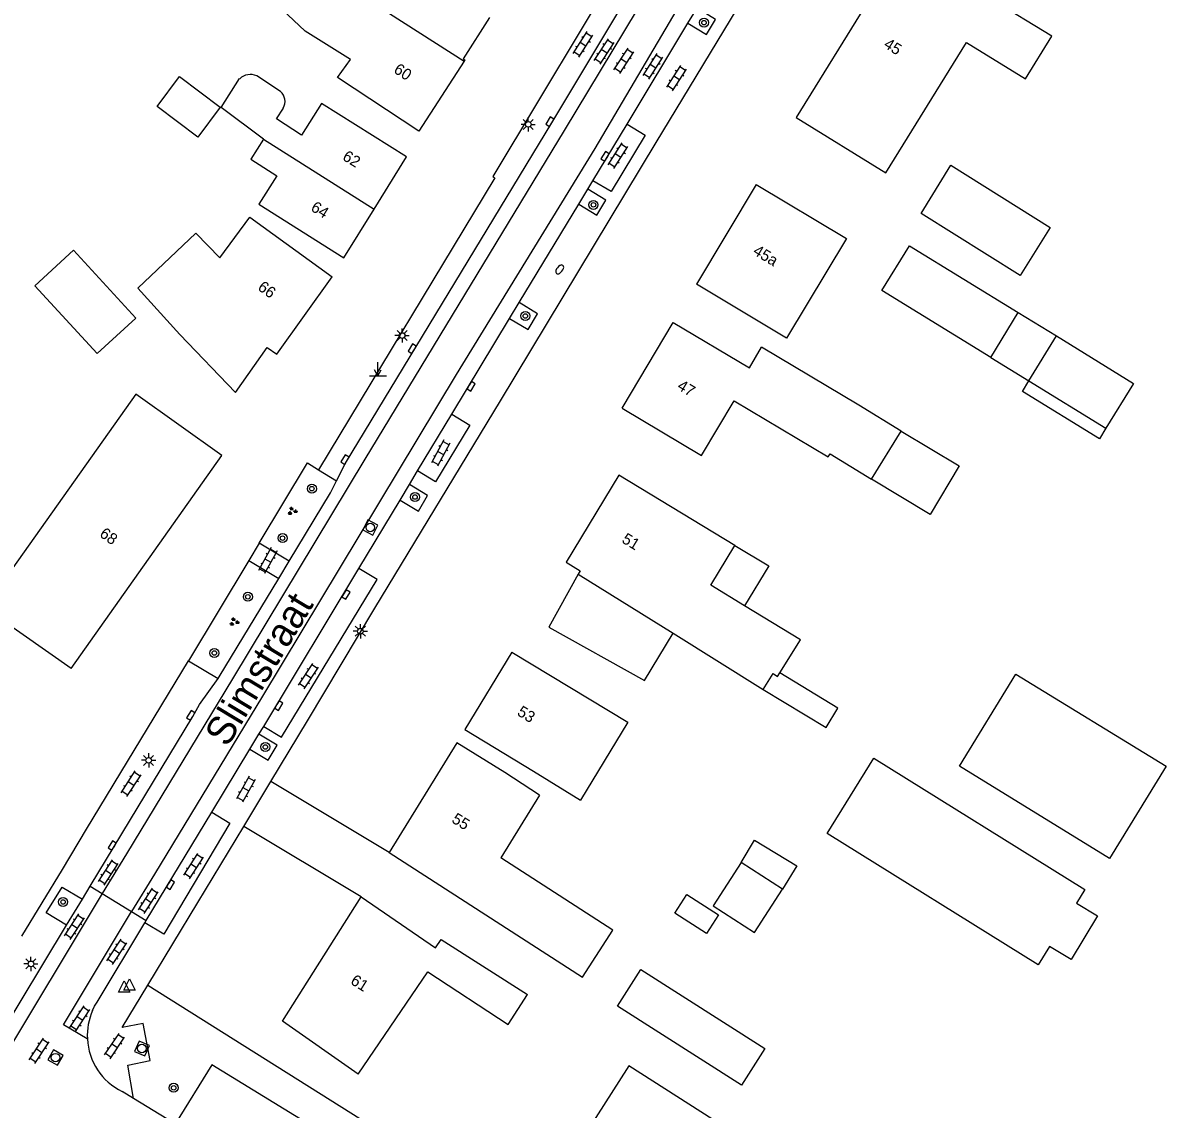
# Model space of a CAD drawing. Extents: x 136000 to 141014, y 402000 to 403500.
# Drawn here: x 137697.7 to 137798.8, y 402166.6 to 402262.7 of the extents above; entities that cross this region are included whole.
import ezdxf

# ---------------------------------------------------------------- set-up
doc = ezdxf.new("R2010")
doc.units = 0
for name, color, linetype in [('gg-afsc-erfafscheiding', 7, 'Continuous'), ('gg-anno-huisnummerreeks BGT', 7, 'Continuous'), ('gg-anno-openbare ruimte label', 7, 'Continuous'), ('gg-bbg-bijgebouw', 7, 'Continuous'), ('gg-bbg-gedigitaliseerde bebouwing', 7, 'Continuous'), ('gg-bbg-gedigitaliseerde bijgebouw', 7, 'Continuous'), ('gg-bbg-hoofdgebouw', 7, 'Continuous'), ('gg-bbg-luifel en loopbrug', 7, 'Continuous'), ('gg-bbg-tussenscheiding', 7, 'Continuous'), ('gg-knt-onverhard', 7, 'Continuous'), ('gg-knt-verharding', 7, 'Continuous'), ('gg-knt-verharding nz', 7, 'Continuous'), ('gt-symb-boom', 7, 'Continuous'), ('gt-symb-brandkraan', 7, 'Continuous'), ('gt-symb-groenvak', 7, 'Continuous'), ('gt-symb-klinker verharding', 7, 'Continuous'), ('gt-symb-kolk', 7, 'Continuous'), ('gt-symb-lichtmast', 7, 'Continuous'), ('gt-symb-markant object', 7, 'Continuous'), ('gt-symb-rioolschacht', 7, 'Continuous'), ('gt-symb-waterafsluiter', 7, 'Continuous')]:
    doc.layers.add(name, color=color, linetype=linetype)

# ---------------------------------------------------------------- blocks, each defined once
blk = doc.blocks.new('gt0-BOOM')
at = {"layer": 'gt-symb-boom'}
for radius in [0.4, 0.2]:
    blk.add_circle((0, 0), radius, dxfattribs=at)
blk = doc.blocks.new('gt0-BR')
at = {"layer": 'gt-symb-brandkraan'}
for centre, radius, start, end in [((-0.24, 0), 0.206, 107.5669, 252.4331), ((0.6, -2.66), 3, 106.892, 107.5669), ((0, -0.69), 0.938, 73.108, 106.892), ((-0.6, -2.66), 3, 72.4331, 73.108), ((0.24, 0), 0.206, 287.567, 72.4331), ((0.6, 2.66), 3, 252.4331, 253.108), ((0, 0.69), 0.938, 253.108, 286.8921), ((-0.6, 2.66), 3, 286.8921, 287.567)]:
    blk.add_arc(centre, radius, start, end, dxfattribs=at)
blk = doc.blocks.new('gt0-LMAST')
at = {"layer": 'gt-symb-lichtmast'}
for p, q in [((-0.18, 0.17), (-0.45, 0.44)), ((0, 0.25), (0, 0.62)), ((0.17, 0.17), (0.44, 0.44)), ((-0.25, 0), (-0.63, 0)), ((-0.18, -0.18), (-0.45, -0.45)), ((0, -0.25), (0, -0.63)), ((0.44, -0.45), (0.17, -0.18)), ((0.25, 0), (0.62, 0))]:
    blk.add_line(p, q, dxfattribs=at)
blk.add_circle((0, 0), 0.25, dxfattribs=at)
blk = doc.blocks.new('gt0-KOLK')
at = {"layer": 'gt-symb-kolk'}
blk.add_lwpolyline([(0, 0), (0.38, 0), (0.38, 0.4), (-0.37, 0.4), (-0.37, 0), (0, 0)], dxfattribs=at)
blk = doc.blocks.new('gt0-KL1')
at = {"layer": 'gt-symb-klinker verharding'}
for p, q in [((-1.15, 0.3), (1.15, 0.3)), ((-1, -0.3), (-1, 0.3)), ((-0.5, 0.3), (-0.5, 0.45)), ((0, -0.3), (0, 0.3)), ((0.5, 0.3), (0.5, 0.45)), ((1, -0.3), (1, 0.3)), ((-1.15, -0.3), (1.15, -0.3)), ((-0.5, -0.45), (-0.5, -0.3)), ((0.5, -0.45), (0.5, -0.3))]:
    blk.add_line(p, q, dxfattribs=at)
blk = doc.blocks.new('gt0-GRVAK')
at = {"layer": 'gt-symb-groenvak'}
for p, q in [((-0.11, 0.19), (-0.23, 0.24)), ((-0.18, 0.15), (0.09, 0.15)), ((-0.09, 0.21), (-0.16, 0.32)), ((-0.05, 0.21), (-0.05, 0.39)), ((0, 0.21), (0.06, 0.32)), ((0.02, 0.19), (0.13, 0.24)), ((0.26, -0.05), (0.2, 0.06)), ((0.31, -0.05), (0.31, 0.13)), ((0.35, -0.05), (0.41, 0.06)), ((-0.24, -0.23), (-0.36, -0.18)), ((-0.32, -0.26), (-0.05, -0.26)), ((-0.23, -0.21), (-0.29, -0.1)), ((-0.18, -0.2), (-0.18, -0.02)), ((-0.14, -0.21), (-0.07, -0.1)), ((-0.12, -0.23), (0, -0.18)), ((0.24, -0.07), (0.12, -0.02)), ((0.17, -0.11), (0.44, -0.11)), ((0.37, -0.07), (0.49, -0.02))]:
    blk.add_line(p, q, dxfattribs=at)
blk = doc.blocks.new('gt0-RS')
at = {"layer": 'gt-symb-rioolschacht'}
blk.add_lwpolyline([(-0.5, -0.5), (0.5, -0.5), (0.5, 0.5), (-0.5, 0.5)], close=True, dxfattribs=at)
blk.add_circle((0, 0), 0.375, dxfattribs=at)
blk = doc.blocks.new('gt0-WAFSL')
at = {"layer": 'gt-symb-waterafsluiter'}
for p, q in [((-0.5, -0.33), (0, 0.67)), ((0, 0.67), (0.5, -0.33)), ((0.5, -0.33), (-0.5, -0.33))]:
    blk.add_line(p, q, dxfattribs=at)
blk = doc.blocks.new('gt0-MARKOB')
at = {"layer": 'gt-symb-markant object'}
for p, q in [((0, 0), (0, 1.2)), ((-0.75, 0), (0.75, 0)), ((0, 0), (-0.3, 0.52)), ((0, 0), (0.3, 0.52))]:
    blk.add_line(p, q, dxfattribs=at)

msp = doc.modelspace()

# ---------------------------------------------------------------- linework, layer by layer
at = {"layer": 'gg-afsc-erfafscheiding'}
msp.add_lwpolyline([(137708.78, 402177.58), (137742.87, 402156.14), (137738.17, 402148.85)], dxfattribs=at)
at = {"layer": 'gg-bbg-bijgebouw'}
for p, q in [((137783.33, 402233.13), (137785.77, 402237.09)), ((137786.71, 402231.06), (137789.14, 402235.02)), ((137786.71, 402231.06), (137793.52, 402226.87))]:
    msp.add_line(p, q, dxfattribs=at)
for points in [[(137783.33, 402233.13), (137773.71, 402239.05), (137776.15, 402243.01), (137785.77, 402237.09)], [(137789.14, 402235.02), (137795.96, 402230.83), (137793.52, 402226.87)]]:
    msp.add_lwpolyline(points, dxfattribs=at)
at = {"layer": 'gg-bbg-gedigitaliseerde bebouwing'}
for p, q in [((137720.52, 402256.64), (137718.43, 402258.05)), ((137720.16, 402254.22), (137720.78, 402255.18)), ((137771.67, 402228.9), (137763.07, 402234.02)), ((137775.4, 402226.61), (137771.67, 402228.9)), ((137772.78, 402222.35), (137775.4, 402226.61)), ((137769.12, 402224.6), (137772.78, 402222.35)), ((137760.71, 402216.5), (137750.45, 402222.72)), ((137758.58, 402212.99), (137760.71, 402216.5)), ((137761.57, 402211.16), (137758.58, 402212.99)), ((137755.24, 402208.72), (137763.22, 402203.75)), ((137736.82, 402200.2), (137742.91, 402196.52)), ((137742.91, 402196.52), (137747.07, 402193.96)), ((137743.42, 402194.41), (137740.01, 402188.85))]:
    msp.add_line(p, q, dxfattribs=at)
for points in [[(137732.75, 402253.14), (137725.58, 402257.9), (137726.72, 402259.49), (137722.72, 402262), (137715.62, 402268.68), (137716.12, 402269.16), (137711.53, 402274.03)], [(137766.14, 402254.34), (137774.07, 402249.44), (137781.2, 402260.99), (137786.42, 402257.77), (137788.74, 402261.54), (137783.41, 402264.83), (137784.31, 402266.3), (137776.5, 402271.13)], [(137719.01, 402252.42), (137715.27, 402255.22), (137716.91, 402257.79)], [(137731.68, 402250.87), (137724.16, 402255.6), (137722.37, 402252.8), (137720.16, 402254.22)], [(137719.01, 402252.42), (137717.89, 402250.67), (137720.21, 402249.19), (137718.6, 402246.67), (137726.13, 402241.93)], [(137715.16, 402241.93), (137717.82, 402245.52), (137725.09, 402240.24)], [(137707.92, 402239.25), (137713.05, 402244.13), (137715.16, 402241.93)], [(137716.54, 402230.03), (137711.62, 402235.16), (137707.92, 402239.25)], [(137715.34, 402224.45), (137707.73, 402229.86), (137694.33, 402210.97)], [(137750.75, 402228.64), (137757.77, 402224.46), (137760.64, 402229.27), (137768.95, 402224.33), (137769.12, 402224.6)], [(137764.68, 402205.21), (137766.5, 402208.13), (137761.57, 402211.16)], [(137744.26, 402209.27), (137752.71, 402204.54), (137755.24, 402208.72)], [(137740.97, 402207.06), (137751.24, 402200.85), (137747.07, 402193.96)], [(137763.22, 402203.75), (137764.09, 402205.15), (137764.49, 402204.9), (137764.68, 402205.21)], [(137743.42, 402194.41), (137740.37, 402196.4), (137736.11, 402199.03)], [(137747.23, 402178.29), (137749.92, 402182.46), (137740.01, 402188.85)], [(137727.39, 402169.72), (137733.55, 402178.78), (137740.66, 402174.12), (137742.36, 402176.77)]]:
    msp.add_lwpolyline(points, dxfattribs=at)
for centre, radius, start, end in [((137717.89, 402256.68), 1.47, 68.4356, 131.4426), ((137719.78, 402255.76), 1.15, 329.9501, 50.1062)]:
    msp.add_arc(centre, radius, start, end, dxfattribs=at)
at = {"layer": 'gg-bbg-gedigitaliseerde bijgebouw'}
for p, q in [((137761.26, 402188.45), (137758.78, 402184.6)), ((137764.93, 402186.08), (137761.26, 402188.45))]:
    msp.add_line(p, q, dxfattribs=at)
for points in [[(137709.61, 402255.31), (137711.6, 402257.97), (137715.2, 402255.27), (137713.21, 402252.61), (137709.61, 402255.31)], [(137788.6, 402244.61), (137785.93, 402240.36), (137777.17, 402245.86), (137779.82, 402250.12), (137788.6, 402244.61)], [(137698.79, 402239.47), (137702.21, 402242.62), (137707.74, 402236.61), (137704.32, 402233.46), (137698.79, 402239.47)], [(137780.56, 402196.96), (137785.55, 402205.11), (137798.85, 402196.95), (137793.85, 402188.8), (137780.56, 402196.96)], [(137768.87, 402191.02), (137773.01, 402197.66), (137791.67, 402186.04), (137790.91, 402184.83)], [(137788.53, 402181.01), (137787.53, 402179.4), (137768.87, 402191.02)], [(137758.78, 402184.6), (137762.45, 402182.24), (137764.93, 402186.08)], [(137755.41, 402183.96), (137756.46, 402185.6), (137759.25, 402183.8), (137758.19, 402182.17), (137755.41, 402183.96)], [(137790.91, 402184.83), (137792.77, 402183.71), (137790.44, 402179.86), (137788.53, 402181.01)], [(137750.33, 402175.74), (137752.4, 402178.99), (137763.37, 402171.99), (137761.3, 402168.74), (137750.33, 402175.74)], [(137747.73, 402164.81), (137751.49, 402162.41), (137753.41, 402165.41), (137757.07, 402163.07), (137758.75, 402165.7), (137751.32, 402170.44), (137747.73, 402164.81)]]:
    msp.add_lwpolyline(points, dxfattribs=at)
at = {"layer": 'gg-bbg-hoofdgebouw'}
for p, q in [((137776.5, 402271.13), (137766.14, 402254.34)), ((137736.78, 402259.32), (137732.75, 402253.14)), ((137728.8, 402246.23), (137731.68, 402250.87)), ((137762.6, 402248.41), (137757.3, 402239.6)), ((137726.13, 402241.93), (137728.8, 402246.23)), ((137702, 402205.61), (137715.34, 402224.45)), ((137746.86, 402213.94), (137744.26, 402209.27)), ((137702, 402205.61), (137694.33, 402210.97)), ((137740.97, 402207.06), (137736.82, 402200.2)), ((137736.11, 402199.03), (137730.13, 402189.32)), ((137730.13, 402189.32), (137747.23, 402178.29))]:
    msp.add_line(p, q, dxfattribs=at)
for points in [[(137739.02, 402263.2), (137736.68, 402259.53), (137736.85, 402259.42), (137736.78, 402259.32)], [(137762.6, 402248.41), (137770.59, 402243.64), (137765.27, 402234.83), (137757.3, 402239.6)], [(137716.54, 402230.03), (137719.35, 402233.99), (137720.2, 402233.41), (137725.09, 402240.24)], [(137750.75, 402228.64), (137755.26, 402236.21), (137761.99, 402232.2), (137763.07, 402234.02)], [(137750.45, 402222.72), (137745.78, 402215.02), (137747.04, 402214.25), (137746.86, 402213.94)], [(137727.39, 402169.72), (137720.7, 402174.39), (137727.66, 402185.41)], [(137727.66, 402185.41), (137734.24, 402180.9), (137734.72, 402181.64), (137742.36, 402176.77)]]:
    msp.add_lwpolyline(points, dxfattribs=at)
at = {"layer": 'gg-bbg-luifel en loopbrug'}
for p, q in [((137785.77, 402237.09), (137789.14, 402235.02)), ((137783.33, 402233.13), (137786.71, 402231.06))]:
    msp.add_line(p, q, dxfattribs=at)
for points in [[(137793.52, 402226.87), (137792.95, 402225.93), (137786.13, 402230.1), (137786.71, 402231.06)], [(137775.4, 402226.61), (137780.55, 402223.54), (137777.99, 402219.24), (137772.78, 402222.35)], [(137760.71, 402216.5), (137763.7, 402214.69), (137761.57, 402211.16)], [(137763.22, 402203.75), (137768.78, 402200.39), (137769.82, 402202.1), (137764.68, 402205.21)], [(137761.26, 402188.45), (137762.45, 402190.42), (137766.18, 402188.16), (137764.93, 402186.08)]]:
    msp.add_lwpolyline(points, dxfattribs=at)
at = {"layer": 'gg-bbg-tussenscheiding'}
for p, q in [((137728.78, 402264.43), (137736.78, 402259.32)), ((137719.01, 402252.42), (137728.8, 402246.23)), ((137746.86, 402213.94), (137755.24, 402208.72))]:
    msp.add_line(p, q, dxfattribs=at)
at = {"layer": 'gg-knt-onverhard'}
for p, q in [((137730.13, 402189.32), (137719.67, 402195.6)), ((137727.66, 402185.41), (137717.29, 402191.64))]:
    msp.add_line(p, q, dxfattribs=at)
at = {"layer": 'gg-knt-verharding'}
for p, q in [((137756.56, 402262.69), (137757.36, 402264.01)), ((137751.18, 402253.76), (137756.56, 402262.69)), ((137748.16, 402248.76), (137751.18, 402253.76)), ((137747.71, 402248.01), (137748.16, 402248.76)), ((137746.9, 402246.67), (137747.71, 402248.01)), ((137741.63, 402237.97), (137746.9, 402246.67)), ((137740.79, 402236.57), (137741.63, 402237.97)), ((137735.67, 402228.09), (137740.79, 402236.57)), ((137732.65, 402223.08), (137735.67, 402228.09)), ((137723.89, 402223.19), (137725.49, 402222.22)), ((137731.93, 402221.88), (137732.65, 402223.08)), ((137731.1, 402220.5), (137731.93, 402221.88)), ((137727.46, 402214.45), (137731.1, 402220.5)), ((137718.65, 402216.7), (137717.73, 402215.17)), ((137721.3, 402215.11), (137718.65, 402216.7)), ((137717.73, 402215.17), (137712.39, 402206.28)), ((137717.73, 402215.17), (137720.37, 402213.56)), ((137720.37, 402213.56), (137721.3, 402215.11)), ((137719.04, 402200.48), (137727.46, 402214.45)), ((137712.39, 402206.28), (137715.01, 402204.73)), ((137718.62, 402199.8), (137719.04, 402200.48)), ((137717.82, 402198.47), (137718.62, 402199.8)), ((137714.45, 402192.9), (137717.82, 402198.47)), ((137717.29, 402191.64), (137719.67, 402195.6)), ((137708.65, 402183.32), (137714.45, 402192.9)), ((137703.7, 402186.34), (137704.76, 402185.7)), ((137701.61, 402182.89), (137703.01, 402185.19)), ((137704.76, 402185.7), (137707.35, 402184.11)), ((137707.35, 402184.11), (137708.65, 402183.32)), ((137708.53, 402183.11), (137708.65, 402183.32)), ((137710.48, 402165.76), (137707.52, 402167.56))]:
    msp.add_line(p, q, dxfattribs=at)
for points in [[(137719.67, 402195.6), (137722.91, 402200.97), (137728.87, 402210.95), (137739.97, 402229.28), (137753.74, 402252.14), (137762.08, 402265.93), (137788.96, 402309.73)], [(137725.49, 402222.22), (137726.28, 402223.78), (137744.51, 402253.87), (137753.02, 402268.05), (137761.58, 402282.15), (137762.7, 402284.07)], [(137759.93, 402283.45), (137751.23, 402269.03), (137739.3, 402249.13), (137739.49, 402249.01), (137723.89, 402223.19)], [(137756.56, 402262.69), (137758.2, 402261.7), (137759, 402263.03), (137757.36, 402264.01)], [(137746.9, 402246.67), (137748.5, 402245.7), (137749.31, 402247.04), (137747.71, 402248.01)], [(137740.79, 402236.57), (137742.42, 402235.58), (137743.26, 402236.98), (137741.63, 402237.97)], [(137718.65, 402216.7), (137722.9, 402223.79), (137723.89, 402223.19)], [(137721.3, 402215.11), (137724.95, 402221.15), (137725.49, 402222.22)], [(137731.1, 402220.5), (137732.72, 402219.52), (137733.54, 402220.91), (137731.93, 402221.88)], [(137715.01, 402204.73), (137715.11, 402204.87), (137720.37, 402213.56)], [(137697.66, 402181.92), (137701.26, 402187.82), (137703.37, 402191.38), (137712.39, 402206.28)], [(137703.7, 402186.34), (137712.76, 402201.35), (137713.37, 402202.41), (137715.01, 402204.73)], [(137717.82, 402198.47), (137719.43, 402197.49), (137720.24, 402198.83), (137718.62, 402199.8)], [(137708.78, 402177.58), (137713.22, 402184.9), (137717.29, 402191.64)], [(137701.61, 402182.89), (137699.79, 402183.99), (137701.22, 402186.27), (137703.01, 402185.19)], [(137707.52, 402167.56), (137707.02, 402170.5), (137708.99, 402170.92), (137708.37, 402174.21), (137706.53, 402173.84), (137708.78, 402177.58)], [(137736.85, 402149.66), (137740.04, 402154.86), (137714.44, 402170.55), (137711.25, 402165.36)]]:
    msp.add_lwpolyline(points, dxfattribs=at)
at = {"layer": 'gg-knt-verharding nz'}
for p, q in [((137703.01, 402185.19), (137703.7, 402186.34)), ((137704.76, 402185.7), (137691.07, 402162.95)), ((137695.22, 402172.3), (137701.61, 402182.89)), ((137707.52, 402167.56), (137706.51, 402168.18))]:
    msp.add_line(p, q, dxfattribs=at)
for points in [[(137765.05, 402285.49), (137754.12, 402267.36), (137745.6, 402253.2), (137727.99, 402224.13), (137716.28, 402204.7), (137706.9, 402189.21), (137704.76, 402185.7)], [(137765.38, 402279.82), (137756.64, 402265.72), (137748.33, 402251.62), (137736.06, 402231.61), (137718.92, 402203.17), (137709.37, 402187.41), (137707.35, 402184.11)], [(137751.18, 402253.76), (137752.78, 402252.79), (137749.76, 402247.8), (137748.16, 402248.76)], [(137735.67, 402228.09), (137737.28, 402227.12), (137734.24, 402222.12), (137732.65, 402223.08)], [(137719.04, 402200.48), (137720.62, 402199.52), (137729.06, 402213.49), (137727.46, 402214.45)], [(137714.45, 402192.9), (137716.06, 402191.93), (137710.21, 402182.1), (137708.53, 402183.11)], [(137703.44, 402172.84), (137701.34, 402174.07), (137707.35, 402184.11)], [(137703.9, 402175.36), (137704.09, 402175.74), (137704.3, 402176.1), (137708.53, 402183.11)]]:
    msp.add_lwpolyline(points, dxfattribs=at)
for centre, radius, start, end in [((137708.94, 402173.13), 5.5, 156.1331, 183.0371), ((137708.95, 402173.13), 5.51, 183.0284, 243.7817)]:
    msp.add_arc(centre, radius, start, end, dxfattribs=at)

# ---------------------------------------------------------------- block references
at = {"layer": 'gt-symb-boom'}
for p in [(137757.98, 402262.74), (137748.2, 402246.62), (137742.18, 402236.79), (137723.3, 402221.51), (137732.42, 402220.77), (137720.71, 402217.14), (137717.64, 402211.95), (137714.68, 402206.97), (137719.19, 402198.66), (137701.3, 402184.95), (137711.08, 402168.51)]:
    msp.add_blockref('gt0-BOOM', p, dxfattribs=at)
at = {"layer": 'gt-symb-brandkraan', "rotation": 51.73717130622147}
msp.add_blockref('gt0-BR', (137745.22, 402240.91), dxfattribs=at)
at = {"layer": 'gt-symb-groenvak'}
for p in [(137721.56, 402219.53), (137716.42, 402209.73)]:
    msp.add_blockref('gt0-GRVAK', p, dxfattribs=at)
at = {"layer": 'gt-symb-klinker verharding'}
for p, rotation in [((137747.28, 402260.82), 57.326722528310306), ((137749.15, 402260.19), 57.326722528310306), ((137750.89, 402259.36), 57.32672253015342), ((137753.46, 402258.87), 57.32672252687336), ((137755.55, 402257.83), 57.326722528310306), ((137750.38, 402250.97), 57.32672252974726), ((137734.69, 402224.67), -118.74303563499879), ((137719.41, 402215.15), -118.7430356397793), ((137723, 402204.92), 56.83440068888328), ((137707.31, 402195.41), 56.83440068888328), ((137717.46, 402194.93), -118.74303563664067), ((137712.85, 402188.12), 56.83440068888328), ((137705.3, 402187.56), 56.83440068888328), ((137708.84, 402185.05), 56.83440068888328), ((137702.31, 402182.76), 56.83440068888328), ((137706.06, 402180.54), 56.83440069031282), ((137702.79, 402174.63), 56.83440068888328), ((137699.18, 402171.78), 56.83440068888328), ((137705.85, 402172.2), 55.88093715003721)]:
    msp.add_blockref('gt0-KL1', p, dxfattribs=dict(at, rotation=rotation))
at = {"layer": 'gt-symb-kolk'}
for p, rotation in [((137744.51, 402253.87), 58.7884989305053), ((137749.4, 402250.81), 58.817568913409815), ((137732.34, 402233.79), 58.817568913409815), ((137737.22, 402230.67), -121.01219615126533), ((137726.4, 402223.98), 58.47021019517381), ((137726.15, 402212.26), -121.13537485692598), ((137720.21, 402202.42), -121.17134902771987), ((137712.76, 402201.35), 58.86462514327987), ((137705.81, 402189.84), 58.893692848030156), ((137710.63, 402186.59), -121.15336239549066)]:
    msp.add_blockref('gt0-KOLK', p, dxfattribs=dict(at, rotation=rotation))
at = {"layer": 'gt-symb-lichtmast'}
for p in [(137742.44, 402253.74), (137731.28, 402235.06), (137727.59, 402208.9), (137708.87, 402197.48), (137698.46, 402179.47)]:
    msp.add_blockref('gt0-LMAST', p, dxfattribs=at)
at = {"layer": 'gt-symb-markant object'}
msp.add_blockref('gt0-MARKOB', (137729.14, 402231.51), dxfattribs=at)
at = {"layer": 'gt-symb-rioolschacht'}
for p, rotation in [((137728.47, 402218.08), 62.79619014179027), ((137708.27, 402171.99), 66.08830877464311), ((137700.63, 402171.18), 60.28614999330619)]:
    msp.add_blockref('gt0-RS', p, dxfattribs=dict(at, rotation=rotation))
at = {"layer": 'gt-symb-waterafsluiter'}
for p in [(137706.71, 402177.3), (137707.18, 402177.47)]:
    msp.add_blockref('gt0-WAFSL', p, dxfattribs=at)

# ---------------------------------------------------------------- texts
at = {"layer": 'gg-anno-huisnummerreeks BGT'}
for s, rotation, p in [('45', 328.3, (137773.79, 402260.6)), ('60', 326.8, (137730.46, 402258.38)), ('62', 328.2, (137725.93, 402250.66)), ('64', 328.2, (137723.13, 402246.16)), ('45a', 329, (137762.23, 402242.3)), ('66', 324.4, (137718.44, 402239.16)), ('47', 329.2, (137755.53, 402230.36)), ('68', 324.7, (137704.45, 402217.34)), ('51', 328.8, (137750.63, 402216.8)), ('53', 328.8, (137741.38, 402201.52)), ('55', 328.4, (137735.59, 402192.04)), ('61', 327.7, (137726.64, 402177.76))]:
    msp.add_text(s, height=1, rotation=rotation, dxfattribs=at).set_placement(p)
at = {"layer": 'gg-anno-openbare ruimte label'}
msp.add_text('Slimstraat', height=2.5, rotation=58.9, dxfattribs=at).set_placement((137715.83, 402198.56))

doc.saveas('drawing.dxf')
